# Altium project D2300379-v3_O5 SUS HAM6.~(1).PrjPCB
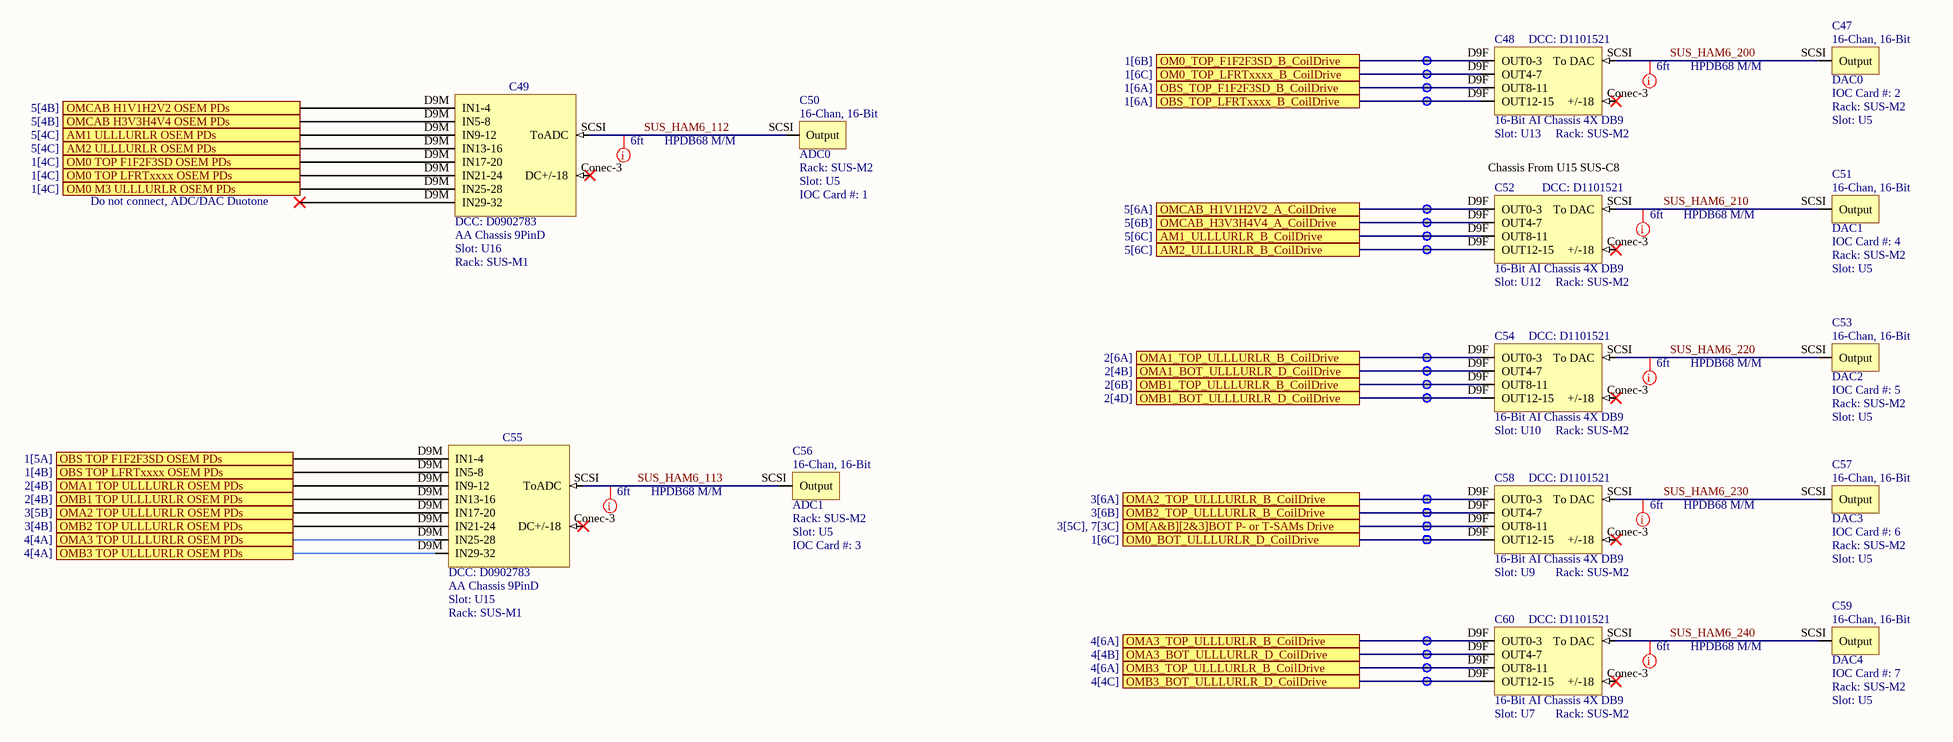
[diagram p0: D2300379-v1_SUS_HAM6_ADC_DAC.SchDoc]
3 sheets, 21 parts. Net scope: flat (ports and power ports of the same name join across sheets).
Sheets:
  D2300379-v1_SUS_HAM6_ADC_DAC.SchDoc
  D2300379-v1_SUSAUXH6_ADC_DAC.SchDoc
  D2300379-v1_RACK_SUS_R7.SchDoc

## Sheet D2300379-v1_SUS_HAM6_ADC_DAC.SchDoc: SUS HAM6 Controls IO Chains
size C; Engineer: L. Sanchez; Organization: LIGO Laboratory; Address1: California Institute of Technology; Address2: Massachusetts Institute of Technology; DocumentNumber: D2300379; Revision: v1; SheetNumber: 6; SheetTotal: 9

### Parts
C47  DAC0  IOC Card #: 2  Rack: SUS-M2  Slot: U5
C48  16-Bit AI Chassis 4X DB9  DCC: D1101521  Rack: SUS-M2  Slot: U13
C49  AA Chassis 9PinD  DCC: D0902783  Rack: SUS-M1  Slot: U16
C50  ADC0  Rack: SUS-M2  Slot: U5  IOC Card #: 1
C51  DAC1  IOC Card #: 4  Rack: SUS-M2  Slot: U5
C52  16-Bit AI Chassis 4X DB9  DCC: D1101521  Rack: SUS-M2  Slot: U12
C53  DAC2  IOC Card #: 5  Rack: SUS-M2  Slot: U5
C54  16-Bit AI Chassis 4X DB9  DCC: D1101521  Rack: SUS-M2  Slot: U10
C55  AA Chassis 9PinD  DCC: D0902783  Rack: SUS-M1  Slot: U15
C56  ADC1  Rack: SUS-M2  Slot: U5  IOC Card #: 3
C57  DAC3  IOC Card #: 6  Rack: SUS-M2  Slot: U5
C58  16-Bit AI Chassis 4X DB9  DCC: D1101521  Rack: SUS-M2  Slot: U9
C59  DAC4  IOC Card #: 7  Rack: SUS-M2  Slot: U5
C60  16-Bit AI Chassis 4X DB9  DCC: D1101521  Rack: SUS-M2  Slot: U7

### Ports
AM1 ULLLURLR OSEM PDs (see 5[4C]), AM1_ULLLURLR_B_CoilDrive (see 5[6C]), AM2 ULLLURLR OSEM PDs (see 5[4C]), AM2_ULLLURLR_B_CoilDrive (see 5[6C]), OBS TOP F1F2F3SD OSEM PDs (see 1[5A]), OBS TOP LFRTxxxx OSEM PDs (see 1[4B]), OBS_TOP_F1F2F3SD_B_CoilDrive (see 1[6A]), OBS_TOP_LFRTxxxx_B_CoilDrive (see 1[6A]), OM0 M3 ULLLURLR OSEM PDs (see 1[4C]), OM0 TOP F1F2F3SD OSEM PDs (see 1[4C]), OM0 TOP LFRTxxxx OSEM PDs (see 1[4C]), OM0_BOT_ULLLURLR_D_CoilDrive (see 1[6C]), OM0_TOP_F1F2F3SD_B_CoilDrive (see 1[6B]), OM0_TOP_LFRTxxxx_B_CoilDrive (see 1[6C]), OM[A&B][2&3]BOT P- or T-SAMs Drive (see 3[5C], 7[3C]), OMA1 TOP ULLLURLR OSEM PDs (see 2[4B]), OMA1_BOT_ULLLURLR_D_CoilDrive (see 2[4B]), OMA1_TOP_ULLLURLR_B_CoilDrive (see 2[6A]), OMA2 TOP ULLLURLR OSEM PDs (see 3[5B]), OMA2_TOP_ULLLURLR_B_CoilDrive (see 3[6A]), OMA3 TOP ULLLURLR OSEM PDs (see 4[4A]), OMA3_BOT_ULLLURLR_D_CoilDrive (see 4[4B]), OMA3_TOP_ULLLURLR_B_CoilDrive (see 4[6A]), OMB1 TOP ULLLURLR OSEM PDs (see 2[4B]), OMB1_BOT_ULLLURLR_D_CoilDrive (see 2[4D]), OMB1_TOP_ULLLURLR_B_CoilDrive (see 2[6B]), OMB2 TOP ULLLURLR OSEM PDs (see 3[4B]), OMB2_TOP_ULLLURLR_B_CoilDrive (see 3[6B]), OMB3 TOP ULLLURLR OSEM PDs (see 4[4A]), OMB3_BOT_ULLLURLR_D_CoilDrive (see 4[4C]), OMB3_TOP_ULLLURLR_B_CoilDrive (see 4[6A]), OMCAB H1V1H2V2 OSEM PDs (see 5[4B]), OMCAB H3V3H4V4 OSEM PDs (see 5[4B]), OMCAB_H1V1H2V2_A_CoilDrive (see 5[6A]), OMCAB_H3V3H4V4_A_CoilDrive (see 5[6B])

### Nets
SUS_HAM6_112: C49.SCSI(ToADC) C50.SCSI(Output)
SUS_HAM6_113: C55.SCSI(ToADC) C56.SCSI(Output)
SUS_HAM6_200: C47.SCSI(Output) C48.SCSI(To_DAC)
SUS_HAM6_210: C51.SCSI(Output) C52.SCSI(To_DAC)
SUS_HAM6_220: C53.SCSI(Output) C54.SCSI(To_DAC)
SUS_HAM6_230: C57.SCSI(Output) C58.SCSI(To_DAC)
SUS_HAM6_240: C59.SCSI(Output) C60.SCSI(To_DAC)
NetC48_D9F: C48.D9F(OUT0-3) ; port OM0_TOP_F1F2F3SD_B_CoilDrive
NetC48_D9F: C48.D9F(OUT4-7) ; port OM0_TOP_LFRTxxxx_B_CoilDrive  [a separate net that carries the same name]
NetC48_D9F: C48.D9F(OUT8-11) ; port OBS_TOP_F1F2F3SD_B_CoilDrive  [a separate net that carries the same name]
NetC48_D9F: C48.D9F(OUT12-15) ; port OBS_TOP_LFRTxxxx_B_CoilDrive  [a separate net that carries the same name]
NetC49_D9M: C49.D9M(IN1-4) ; port OMCAB H1V1H2V2 OSEM PDs
NetC49_D9M: C49.D9M(IN5-8) ; port OMCAB H3V3H4V4 OSEM PDs  [a separate net that carries the same name]
NetC49_D9M: C49.D9M(IN9-12) ; port AM1 ULLLURLR OSEM PDs  [a separate net that carries the same name]
NetC49_D9M: C49.D9M(IN13-16) ; port AM2 ULLLURLR OSEM PDs  [a separate net that carries the same name]
NetC49_D9M: C49.D9M(IN17-20) ; port OM0 TOP F1F2F3SD OSEM PDs  [a separate net that carries the same name]
NetC49_D9M: C49.D9M(IN21-24) ; port OM0 TOP LFRTxxxx OSEM PDs  [a separate net that carries the same name]
NetC49_D9M: C49.D9M(IN25-28) ; port OM0 M3 ULLLURLR OSEM PDs  [a separate net that carries the same name]
NetC52_D9F: C52.D9F(OUT0-3) ; port OMCAB_H1V1H2V2_A_CoilDrive
NetC52_D9F: C52.D9F(OUT4-7) ; port OMCAB_H3V3H4V4_A_CoilDrive  [a separate net that carries the same name]
NetC52_D9F: C52.D9F(OUT8-11) ; port AM1_ULLLURLR_B_CoilDrive  [a separate net that carries the same name]
NetC52_D9F: C52.D9F(OUT12-15) ; port AM2_ULLLURLR_B_CoilDrive  [a separate net that carries the same name]
NetC54_D9F: C54.D9F(OUT0-3) ; port OMA1_TOP_ULLLURLR_B_CoilDrive
NetC54_D9F: C54.D9F(OUT4-7) ; port OMA1_BOT_ULLLURLR_D_CoilDrive  [a separate net that carries the same name]
NetC54_D9F: C54.D9F(OUT8-11) ; port OMB1_TOP_ULLLURLR_B_CoilDrive  [a separate net that carries the same name]
NetC54_D9F: C54.D9F(OUT12-15) ; port OMB1_BOT_ULLLURLR_D_CoilDrive  [a separate net that carries the same name]
NetC55_D9M: C55.D9M(IN1-4) ; port OBS TOP F1F2F3SD OSEM PDs
NetC55_D9M: C55.D9M(IN5-8) ; port OBS TOP LFRTxxxx OSEM PDs  [a separate net that carries the same name]
NetC55_D9M: C55.D9M(IN9-12) ; port OMA1 TOP ULLLURLR OSEM PDs  [a separate net that carries the same name]
NetC55_D9M: C55.D9M(IN13-16) ; port OMB1 TOP ULLLURLR OSEM PDs  [a separate net that carries the same name]
NetC55_D9M: C55.D9M(IN17-20) ; port OMA2 TOP ULLLURLR OSEM PDs  [a separate net that carries the same name]
NetC55_D9M: C55.D9M(IN21-24) ; port OMB2 TOP ULLLURLR OSEM PDs  [a separate net that carries the same name]
NetC55_D9M: C55.D9M(IN25-28) ; port OMA3 TOP ULLLURLR OSEM PDs  [a separate net that carries the same name]
NetC55_D9M: C55.D9M(IN29-32) ; port OMB3 TOP ULLLURLR OSEM PDs  [a separate net that carries the same name]
NetC58_D9F: C58.D9F(OUT0-3) ; port OMA2_TOP_ULLLURLR_B_CoilDrive
NetC58_D9F: C58.D9F(OUT4-7) ; port OMB2_TOP_ULLLURLR_B_CoilDrive  [a separate net that carries the same name]
NetC58_D9F: C58.D9F(OUT8-11) ; port OM[A&B][2&3]BOT P- or T-SAMs Drive  [a separate net that carries the same name]
NetC58_D9F: C58.D9F(OUT12-15) ; port OM0_BOT_ULLLURLR_D_CoilDrive  [a separate net that carries the same name]
NetC60_D9F: C60.D9F(OUT0-3) ; port OMA3_TOP_ULLLURLR_B_CoilDrive
NetC60_D9F: C60.D9F(OUT4-7) ; port OMA3_BOT_ULLLURLR_D_CoilDrive  [a separate net that carries the same name]
NetC60_D9F: C60.D9F(OUT8-11) ; port OMB3_TOP_ULLLURLR_B_CoilDrive  [a separate net that carries the same name]
NetC60_D9F: C60.D9F(OUT12-15) ; port OMB3_BOT_ULLLURLR_D_CoilDrive  [a separate net that carries the same name]

Not connected (* = marked no-connect by the designer): C48 Conec-3(+/-18)*; C49 Conec-3(DC+/-18)*; C52 Conec-3(+/-18)*; C54 Conec-3(+/-18)*; C55 Conec-3(DC+/-18)*; C58 Conec-3(+/-18)*; C60 Conec-3(+/-18)*

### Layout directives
Length: 6ft; DCC: HPDB68 M/M: SUS_HAM6_112, SUS_HAM6_113, SUS_HAM6_200, SUS_HAM6_210, SUS_HAM6_220, SUS_HAM6_230, SUS_HAM6_240

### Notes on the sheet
- Do not connect, ADC/DAC Duotone
- (near C52) Chassis From U15 SUS-C8

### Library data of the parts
C47 C51 C53 C57 C59 = DAC-16: 16 Chan, 16 Bit DAC
C48 C52 C54 C58 C60 = AI_9pin_16_bit: AI Chassis 4X DB9 16-bit; Serial: Sxxxxxxx; System: ISC
C49 C55 = AA_9pinAll: ISC AA Chassis 9PinD; Serial: Sxxxxxxx
C50 C56 = ADC-16: 16 Chan, 16 Bit ADC

## Sheet D2300379-v1_SUSAUXH6_ADC_DAC.SchDoc: SUS AUX HAM6 Coil Mon. IO Chains
size B; Engineer: L. Sanchez; Organization: LIGO Laboratory; Address1: California Institute of Technology; Address2: Massachusetts Institute of Technology; DocumentNumber: D2300379; Revision: v1; SheetNumber: 7; SheetTotal: 9
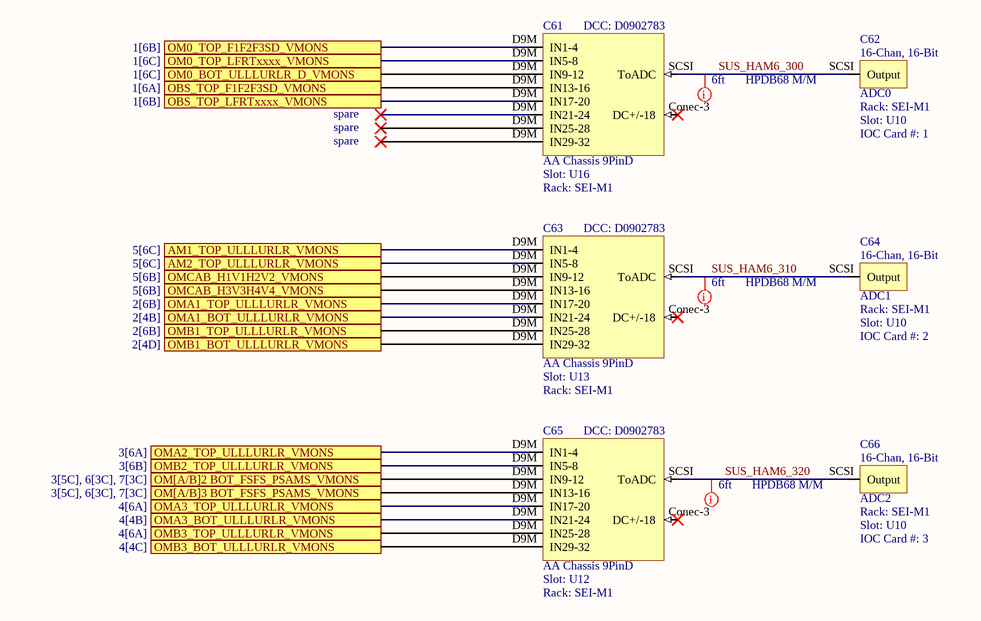
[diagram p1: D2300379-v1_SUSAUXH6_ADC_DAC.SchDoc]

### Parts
C61  AA Chassis 9PinD  Slot: U16  Rack: SEI-M1  DCC: D0902783
C62  ADC0  Rack: SEI-M1  Slot: U10  IOC Card #: 1
C63  AA Chassis 9PinD  Slot: U13  Rack: SEI-M1  DCC: D0902783
C64  ADC1  Rack: SEI-M1  Slot: U10  IOC Card #: 2
C65  AA Chassis 9PinD  Slot: U12  Rack: SEI-M1  DCC: D0902783
C66  ADC2  Rack: SEI-M1  Slot: U10  IOC Card #: 3

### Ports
AM1_TOP_ULLLURLR_VMONS (see 5[6C]), AM2_TOP_ULLLURLR_VMONS (see 5[6C]), OBS_TOP_F1F2F3SD_VMONS (see 1[6A]), OBS_TOP_LFRTxxxx_VMONS (see 1[6B]), OM0_BOT_ULLLURLR_D_VMONS (see 1[6C]), OM0_TOP_F1F2F3SD_VMONS (see 1[6B]), OM0_TOP_LFRTxxxx_VMONS (see 1[6C]), OM[A/B]2 BOT_FSFS_PSAMS_VMONS (see 3[5C], 6[3C], 7[3C]), OM[A/B]3 BOT_FSFS_PSAMS_VMONS (see 3[5C], 6[3C], 7[3C]), OMA1_BOT_ULLLURLR_VMONS (see 2[4B]), OMA1_TOP_ULLLURLR_VMONS (see 2[6B]), OMA2_TOP_ULLLURLR_VMONS (see 3[6A]), OMA3_BOT_ULLLURLR_VMONS (see 4[4B]), OMA3_TOP_ULLLURLR_VMONS (see 4[6A]), OMB1_BOT_ULLLURLR_VMONS (see 2[4D]), OMB1_TOP_ULLLURLR_VMONS (see 2[6B]), OMB2_TOP_ULLLURLR_VMONS (see 3[6B]), OMB3_BOT_ULLLURLR_VMONS (see 4[4C]), OMB3_TOP_ULLLURLR_VMONS (see 4[6A]), OMCAB_H1V1H2V2_VMONS (see 5[6B]), OMCAB_H3V3H4V4_VMONS (see 5[6B])

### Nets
SUS_HAM6_300: C61.SCSI(ToADC) C62.SCSI(Output)
SUS_HAM6_310: C63.SCSI(ToADC) C64.SCSI(Output)
SUS_HAM6_320: C65.SCSI(ToADC) C66.SCSI(Output)
NetC61_D9M: C61.D9M(IN1-4) ; port OM0_TOP_F1F2F3SD_VMONS
NetC61_D9M: C61.D9M(IN5-8) ; port OM0_TOP_LFRTxxxx_VMONS  [a separate net that carries the same name]
NetC61_D9M: C61.D9M(IN9-12) ; port OM0_BOT_ULLLURLR_D_VMONS  [a separate net that carries the same name]
NetC61_D9M: C61.D9M(IN13-16) ; port OBS_TOP_F1F2F3SD_VMONS  [a separate net that carries the same name]
NetC61_D9M: C61.D9M(IN17-20) ; port OBS_TOP_LFRTxxxx_VMONS  [a separate net that carries the same name]
NetC63_D9M: C63.D9M(IN1-4) ; port AM1_TOP_ULLLURLR_VMONS
NetC63_D9M: C63.D9M(IN5-8) ; port AM2_TOP_ULLLURLR_VMONS  [a separate net that carries the same name]
NetC63_D9M: C63.D9M(IN9-12) ; port OMCAB_H1V1H2V2_VMONS  [a separate net that carries the same name]
NetC63_D9M: C63.D9M(IN13-16) ; port OMCAB_H3V3H4V4_VMONS  [a separate net that carries the same name]
NetC63_D9M: C63.D9M(IN17-20) ; port OMA1_TOP_ULLLURLR_VMONS  [a separate net that carries the same name]
NetC63_D9M: C63.D9M(IN21-24) ; port OMA1_BOT_ULLLURLR_VMONS  [a separate net that carries the same name]
NetC63_D9M: C63.D9M(IN25-28) ; port OMB1_TOP_ULLLURLR_VMONS  [a separate net that carries the same name]
NetC63_D9M: C63.D9M(IN29-32) ; port OMB1_BOT_ULLLURLR_VMONS  [a separate net that carries the same name]
NetC65_D9M: C65.D9M(IN1-4) ; port OMA2_TOP_ULLLURLR_VMONS
NetC65_D9M: C65.D9M(IN5-8) ; port OMB2_TOP_ULLLURLR_VMONS  [a separate net that carries the same name]
NetC65_D9M: C65.D9M(IN9-12) ; port OM[A/B]2 BOT_FSFS_PSAMS_VMONS  [a separate net that carries the same name]
NetC65_D9M: C65.D9M(IN13-16) ; port OM[A/B]3 BOT_FSFS_PSAMS_VMONS  [a separate net that carries the same name]
NetC65_D9M: C65.D9M(IN17-20) ; port OMA3_TOP_ULLLURLR_VMONS  [a separate net that carries the same name]
NetC65_D9M: C65.D9M(IN21-24) ; port OMA3_BOT_ULLLURLR_VMONS  [a separate net that carries the same name]
NetC65_D9M: C65.D9M(IN25-28) ; port OMB3_TOP_ULLLURLR_VMONS  [a separate net that carries the same name]
NetC65_D9M: C65.D9M(IN29-32) ; port OMB3_BOT_ULLLURLR_VMONS  [a separate net that carries the same name]

Not connected (* = marked no-connect by the designer): C61 Conec-3(DC+/-18)*; C63 Conec-3(DC+/-18)*; C65 Conec-3(DC+/-18)*

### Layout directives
Length: 6ft; DCC: HPDB68 M/M: SUS_HAM6_300, SUS_HAM6_310, SUS_HAM6_320

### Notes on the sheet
- spare

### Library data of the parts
C61 C63 C65 = AA_9pinAll: ISC AA Chassis 9PinD; Serial: Sxxxxxxx
C62 C64 C66 = ADC-16: 16 Chan, 16 Bit ADC

## Sheet D2300379-v1_RACK_SUS_R7.SchDoc: FIELD RACK SUS-R7
size C; Engineer: L. Sanchez; Organization: LIGO Laboratory; Address1: California Institute of Technology; Address2: Massachusetts Institute of Technology; DocumentNumber: D2300379; Revision: v1; SheetNumber: 8; SheetTotal: 9
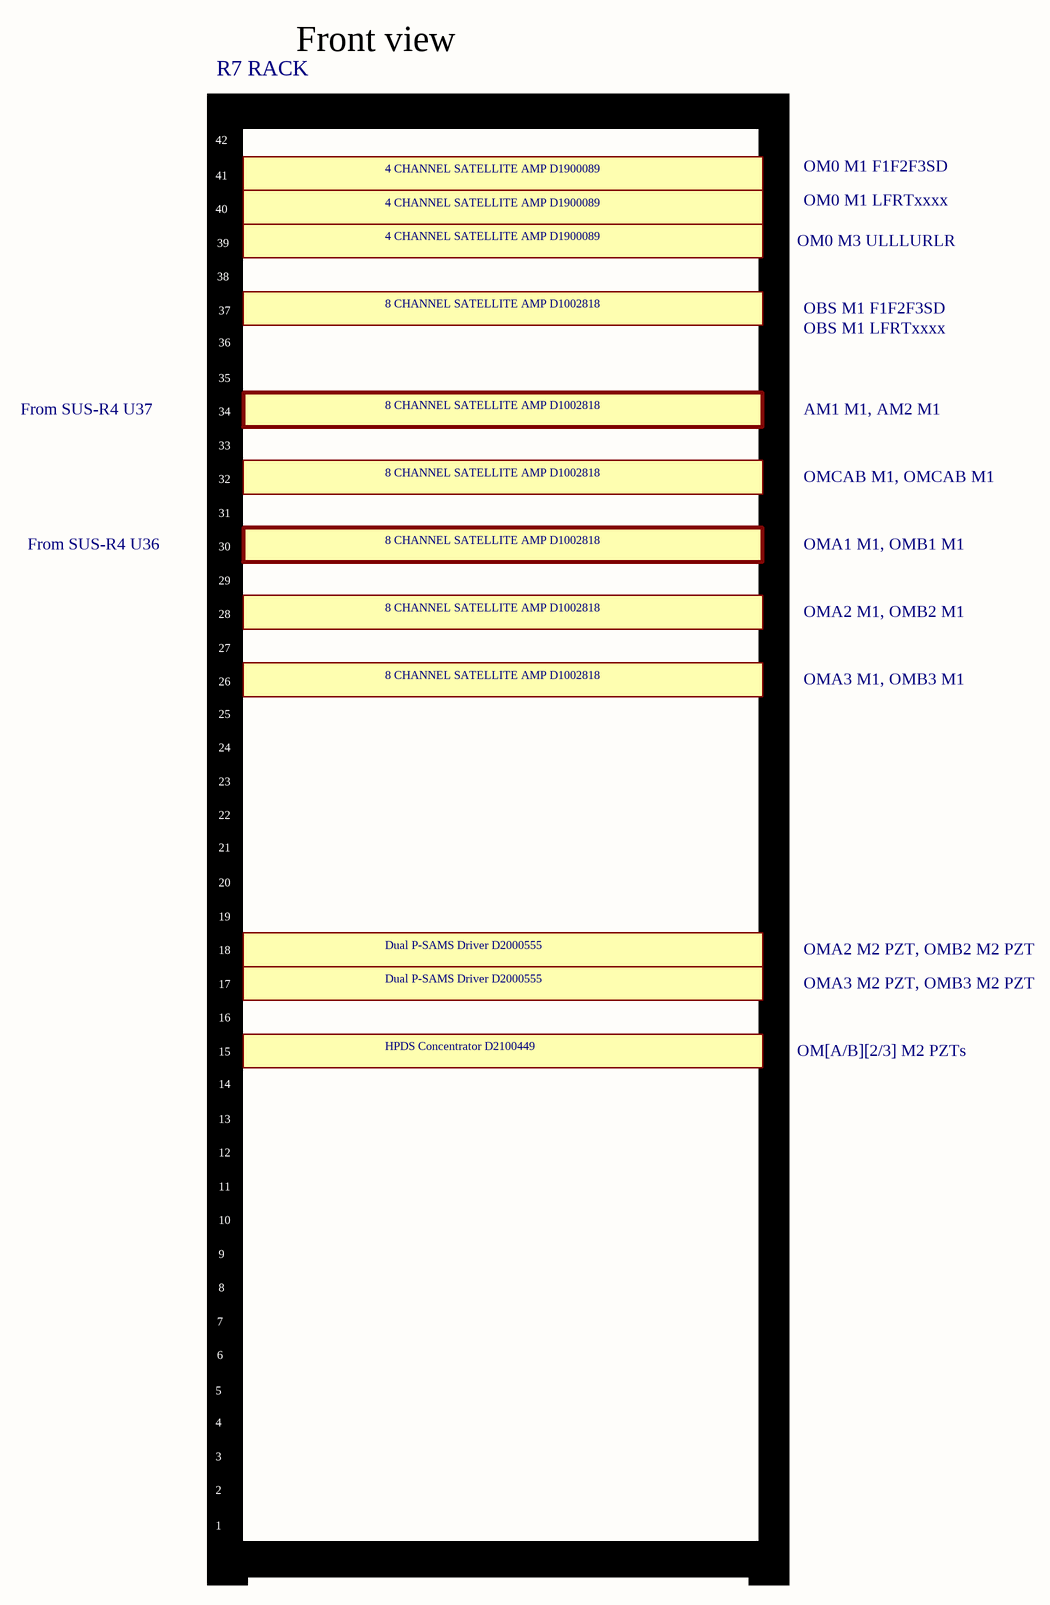
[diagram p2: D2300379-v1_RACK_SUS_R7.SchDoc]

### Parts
RackR2  1U  Rack 42 pos  (value not drawn)  (part A of 2)

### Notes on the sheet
- Front view
- R7 RACK
- 4 CHANNEL SATELLITE AMP D1900089
- OM0 M1 F1F2F3SD
- OM0 M3 ULLLURLR
- OM0 M1 LFRTxxxx
- 8 CHANNEL SATELLITE AMP D1002818
- OBS M1 F1F2F3SD
- OBS M1 LFRTxxxx
- From SUS-R4 U37
- AM1 M1, AM2 M1
- OMCAB M1, OMCAB M1
- From SUS-R4 U36
- OMA1 M1, OMB1 M1
- OMA2 M1, OMB2 M1
- OMA3 M1, OMB3 M1
- Dual P-SAMS Driver D2000555
- OMA3 M2 PZT, OMB3 M2 PZT
- OMA2 M2 PZT, OMB2 M2 PZT
- HPDS Concentrator D2100449
- OM[A/B][2/3] M2 PZTs

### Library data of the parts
RackR2 = RACK_42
